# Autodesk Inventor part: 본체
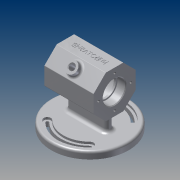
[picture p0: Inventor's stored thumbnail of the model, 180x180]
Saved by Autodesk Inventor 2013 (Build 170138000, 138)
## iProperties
Created: 2017-06
Part Number: 본체
Material: 알루미늄 6061
Document SubType Name: Modeling
Designer: Administrator
Density: 2.71 g/cm^3
Mass: 562.521 g
Surface Area: 565.555 cm^2
Volume: 207.572 cm^3
Author: Administrator
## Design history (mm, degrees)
sketch "스케치2" dims "d4" = 60
  geometry: L1 (30, -12.426)-(12.426, -30); L2 (12.426, -30)-(-12.426, -30); L3 (-12.426, -30)-(-30, -12.426); L4 (-30, -12.426)-(-30, 12.426); L5 (-30, 12.426)-(-12.426, 30); L6 (-12.426, 30)-(12.426, 30); L7 (12.426, 30)-(30, 12.426); L8 (30, 12.426)-(30, -12.426); 4 further points
  constraints: 16 end point, 2 coincident, 1 horizontal alignment, 1 midpoint, 19 other
  dimensions: "d5" = 17.57359 horizontal distance of L6.end L7.end
extrude "돌출2" new body sketch "스케치2" distance "d6" = 70; taper "d7" = 0 deg
sketch "스케치3"
  geometry: L1 (0, 0)-(12, 0); L2 (12, 0)-(12, 16); L3 (12, 16)-(0, 16); L4 (0, 16)-(0, 0); L5 (12, 0)-(15, 0); L6 (15, 0)-(15, 14); L7 (15, 14)-(12, 14); L8 (12, 14)-(12, 0); L9 (15, 0)-(55, 0); L10 (55, 0)-(55, 25); L11 (55, 25)-(15, 25); L12 (15, 25)-(15, 0); L13 (55, 0)-(58, 0); L14 (58, 0)-(58, 14); L15 (58, 14)-(55, 14); L16 (55, 14)-(55, 0); L17 (58, 0)-(70, 0); L18 (70, 0)-(70, 16); L19 (70, 16)-(58, 16); L20 (58, 16)-(58, 0); L21 (15, 0)-(55, 0)
  constraints: 42 end point, 11 equal length, 5 horizontal, 5 perpendicular
  dimensions: "d8" = 16 distance between parallel lines of L1 L3; "d10" = 12 distance of L2.end L3.end; "d11" = 3 distance of L6.end L7.end; "d12" = 14 distance between parallel lines of L5 L7; "d13" = 25 distance between parallel lines of L9 L11; "d14" = 40 distance of L10.end L11.end; "d15" = 3 distance of L14.end L15.end; "d16" = 14 distance between parallel lines of L13 L15; "d17" = 12 distance of L18.end L19.end; "d18" = 16 distance between parallel lines of L19 L17
revolve "회전1" sketch "스케치3" stored, may be unused: angle "d19" = 90 deg
chamfer "모따기1" distance "d20" = 1; stored, may be unused: second distance "d21" = 2, angle "d22" = 45 deg
fillet "모깎기1" dims "d23" = 0.3
fillet "모깎기2" dims "d24" = 3
sketch "스케치4"
  geometry: C1 r 17 at (0, 0) reference; 1 further point
  constraints: 1 vertical alignment
  dimensions: "d25" = 23 distance of point (0, 23) C1.centre
hole "구멍1" sketch "스케치4" at (0, 23) diameter "d26" = 3.242; stored, may be unused: countersink angle "d30" = 90 deg, drill point angle "d32" = 118 deg; dims "d27" = 8, "d28" = 4, "d29" = 2, "d31" = 10
node "작업 평면1"
sketch "스케치5"
  geometry: L1 (0, 42.426)-(70, 42.426) reference; C1 r 8 at (35, 12.426); 1 further point
  constraints: 1 centre point
  dimensions: "d36" = 16 diameter of C1; "d37" = 35 distance of point (0, 12.426) C1.centre; "d38" = 30 distance from line of C1.centre L1
extrude "돌출3" join sketch "스케치5" distance "d39" = 7; taper "d40" = 0 deg
sketch "스케치6"
  geometry: C1 r 8 at (0, 0) reference; C2 r 4 at (0, 0); 1 further point
  constraints: 1 centre point, 1 coincident
  dimensions: "d41" = 8 diameter of C2
extrude "돌출4" cut sketch "스케치6" distance "d42" = 40; taper "d43" = 0 deg
fillet "모깎기3" dims "d44" = 3
chamfer "모따기2" distance "d45" = 1; stored, may be unused: second distance "d46" = 2, angle "d47" = 45 deg
node "작업 평면2"
sketch "스케치7" dims "d49" = 110
  geometry: L1 (0, -30)-(-70, -30) reference; L2 (0, 30)-(-70, 30) reference; L3 (-70, -12.426)-(-70, 12.426) reference; L4 (-70, -30)-(-70, -12.426) reference; L5 (0, -12.426)-(0, -30) reference; 3 further points
  constraints: 2 vertical alignment, 1 horizontal alignment, 2 other
  dimensions: "d51" = 35 distance of point (-35, 0) point (0, 0)
extrude "돌출5" join sketch "스케치7" distance "d52" = 10; taper "d53" = 0 deg
fillet "모깎기4" dims "d54" = 3
sketch "스케치8"
  geometry: L1 (0, 0)-(0, 74.505); L2 (0, 0)-(-54.26, 54.26); L3 (0, 0)-(48.488, 48.488); C1 r 52 at (0, 0) reference; A1 r 48 centre (0, 0) between (33.941, 33.941) and (-33.941, 33.941); A2 r 38 centre (0, 0) between (26.87, 26.87) and (-26.87, 26.87); A3 r 5 centre (30.406, 30.406) between (26.87, 26.87) and (33.941, 33.941); A4 r 5 centre (-30.406, 30.406) between (-33.941, 33.941) and (-26.87, 26.87); 1 further point
  constraints: 8 point on circle, 6 end point, 4 centre point, 4 point on line, 2 coincident, 2 tangent, 1 vertical
  dimensions: "d55" = 96 diameter of A1; "d56" = 76 diameter of A2; "d57" = 45 deg angle of L3 L1; "d58" = 45 deg angle of L1 L2; "d60" = 5 radius of A3; "d61" = 48.48819 distance from line of L3.end L1; "d62" = 52.68307 distance from line of L1.end L3; "d63" = 76.73489 distance from line of L2.end L3
extrude "돌출6" cut sketch "스케치8" distance "d64" = 3; taper "d65" = 0 deg
sketch "스케치9"
  geometry: A1 r 5 centre (30.406, 30.406) between (26.87, 26.87) and (33.941, 33.941) reference; A2 r 48 centre (0, 0) between (33.941, 33.941) and (-33.941, 33.941) reference; A3 r 5 centre (-30.406, 30.406) between (-33.941, 33.941) and (-26.87, 26.87) reference; A4 r 2 centre (-30.406, 30.406) between (-31.82, 31.82) and (-28.991, 28.991); A5 r 2 centre (30.406, 30.406) between (28.991, 28.991) and (31.82, 31.82); A6 r 41 centre (0, 0) between (28.991, 28.991) and (-28.991, 28.991); A7 r 43 centre (0, 0) between (31.787, 28.959) and (-31.787, 28.959); A8 r 45 centre (0, 0) between (31.82, 31.82) and (-31.82, 31.82); 1 further point
  constraints: 12 point on circle, 5 centre point, 3 coincident
  dimensions: "d67" = 4 diameter of A4; "d68" = 4 diameter of A5; "d69" = 41 radius of A6; "d70" = 43 radius of A7; "d71" = 45 radius of A8
extrude "돌출7" cut sketch "스케치9" distance "d72" = 7; taper "d73" = 0 deg
sketch "스케치10"
  geometry: L1 (-24, 5)-(24, 5); L2 (24, 5)-(24, -5); L3 (24, -5)-(-24, -5); L4 (-24, -5)-(-24, 5); A1 r 48 centre (0, 0) between (-33.941, -33.941) and (33.941, -33.941) reference; A2 r 5 centre (24, 0) between (24, -5) and (24, 5); A3 r 5 centre (-24, 0) between (-24, 5) and (-24, -5); 3 further points
  constraints: 8 end point, 4 point on circle, 4 tangent, 2 centre point, 2 midpoint, 2 parallel, 1 horizontal, 1 horizontal alignment, 1 perpendicular, 1 vertical alignment
  dimensions: "d74" = 48 distance between parallel lines of L4 L2; "d76" = 10 distance of L3.end L1.start
extrude "돌출8" join sketch "스케치10" stored distance "d77" = 7; taper "d78" = 0 deg
fillet "모깎기5" dims "d79" = 5
fillet "모깎기6" dims "d80" = 1
node "작업 평면3"
sketch "스케치11"
  geometry: L1 (10.113, 16.755)-(59.887, 16.755); L2 (59.887, 16.755)-(59.887, 6.684); L3 (59.887, 6.684)-(10.113, 6.684); L4 (10.113, 6.684)-(10.113, 16.755); L5 (0, 24.731)-(0, 41.719) reference; L6 (0, 41.719)-(70, 41.719) reference; L7 (70, 41.719)-(70, 24.731) reference; 3 further points
  constraints: 2 midpoint, 1 parallel, 2 other
  dimensions: "d82" = 35 distance from line of point (35, 16.755) L5; "d83" = 30 distance from line of L6 point (59.887, 11.719); "d84" = 24.96431 distance from line of L6 point (35, 16.755); "d85" = 10.11262 distance from line of L7 point (59.887, 11.719)
feature "엠보싱1" sketch "스케치11" dims "d8" = 16, "d10" = 12, "d11" = 3, "d12" = 14, "d13" = 25, "d14" = 40, "d15" = 3, "d16" = 14, "d17" = 12, "d18" = 16, "d86" = 0.5, "d87" = 0
node "솔리드2"
pattern_circular "원형 패턴1" dims angle "d34" = 360 deg
mirror "대칭1"
mirror "대칭2"
other parameters: "d48" = -62, "d66" = 86, "d81" = 0.5
